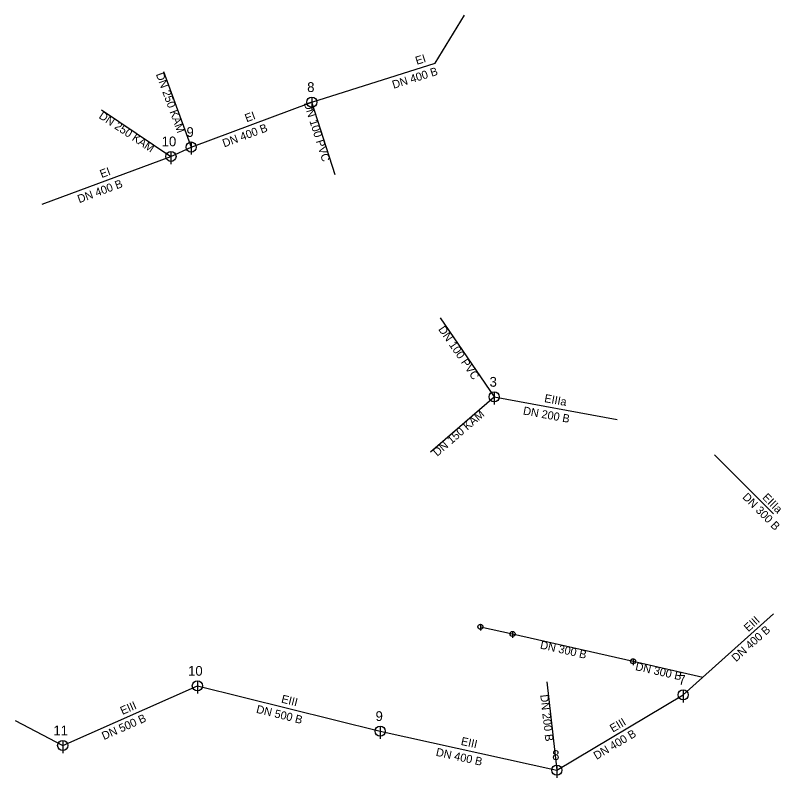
# Model space of a CAD drawing. Extents: x -447725 to -447574, y -1113374 to -1113224.
import ezdxf

# ---------------------------------------------------------------- set-up
doc = ezdxf.new("R2010")
doc.units = 0
for name, color, linetype in [('_pripojka_kanal_jednotna_prevzato_z_dokumentace_', 7, 'Continuous'), ('_pripojka_kanal_jednotna_priblizne_', 7, 'Continuous'), ('_stoka_jednotna_smvak_prevzato_z_dokumentace_', 7, 'Continuous'), ('Default', 7, 'Continuous'), ('MoLevel 119', 7, 'Continuous'), ('MoLevel 120', 7, 'Continuous'), ('MoLevel 124', 7, 'Continuous'), ('MoLevel 126', 7, 'Continuous'), ('MoLevel 57', 7, 'Continuous'), ('MoLevel 68', 7, 'Continuous'), ('MoLevel 69', 7, 'Continuous')]:
    doc.layers.add(name, color=color, linetype=linetype)

# ---------------------------------------------------------------- blocks, each defined once
blk = doc.blocks.new('_sachta_kanal_prip_')
at = {"layer": 'Default'}
blk.add_line((0, 0.00005), (0, -0.000075), dxfattribs=at)
blk.add_circle((0, 0), 0.00005, dxfattribs=at)
blk = doc.blocks.new('_sachta_kanal_prevzato_z_dokumentace_')
at = {"layer": 'Default'}
blk.add_line((0, 0.00005), (0, -0.000075), dxfattribs=at)
blk.add_circle((0, 0), 0.00005, dxfattribs=at)

msp = doc.modelspace()

# ---------------------------------------------------------------- linework, layer by layer
at = {"layer": '_pripojka_kanal_jednotna_prevzato_z_dokumentace_'}
msp.add_line((-447626.69, -1113346.07), (-447602.89, -1113351.46), dxfattribs=at)
at = {"layer": '_pripojka_kanal_jednotna_priblizne_'}
for p, q in [((-447695.62, -1113234.93), (-447690.13, -1113249.88)), ((-447661.72, -1113255.38), (-447666.3, -1113241)), ((-447707.86, -1113242.56), (-447694.11, -1113251.73)), ((-447640.99, -1113283.65), (-447630.29, -1113299.23)), ((-447642.87, -1113310.1), (-447630.29, -1113299.23)), ((-447633.03, -1113344.66), (-447626.69, -1113346.07)), ((-447602.89, -1113351.46), (-447589.09, -1113354.59)), ((-447619.88, -1113355.52), (-447617.93, -1113372.96))]:
    msp.add_line(p, q, dxfattribs=at)
at = {"layer": '_stoka_jednotna_smvak_prevzato_z_dokumentace_'}
for p, q in [((-447690.13, -1113249.88), (-447666.3, -1113241)), ((-447694.11, -1113251.73), (-447690.13, -1113249.88)), ((-447719.55, -1113261.19), (-447694.11, -1113251.73)), ((-447630.29, -1113299.23), (-447606.03, -1113303.7)), ((-447586.79, -1113310.65), (-447575.16, -1113322.36)), ((-447593, -1113358.1), (-447575.16, -1113342.08)), ((-447715.49, -1113368.09), (-447688.9, -1113356.32)), ((-447688.9, -1113356.32), (-447652.8, -1113365.26)), ((-447617.93, -1113372.96), (-447593, -1113358.1)), ((-447724.85, -1113363.18), (-447715.49, -1113368.09)), ((-447652.8, -1113365.26), (-447617.93, -1113372.96))]:
    msp.add_line(p, q, dxfattribs=at)
msp.add_lwpolyline([(-447666.3, -1113241), (-447641.94, -1113233.3), (-447636.17, -1113223.85)], dxfattribs=at)

# ---------------------------------------------------------------- block references
at = {"layer": 'MoLevel 119', "xscale": 20000, "yscale": 20000}
for p in [(-447666.3, -1113241), (-447690.13, -1113249.88), (-447694.11, -1113251.73), (-447630.29, -1113299.23), (-447688.9, -1113356.32), (-447593, -1113358.1), (-447652.8, -1113365.26), (-447715.49, -1113368.09), (-447617.93, -1113372.96)]:
    msp.add_blockref('_sachta_kanal_prevzato_z_dokumentace_', p, dxfattribs=at)
at = {"layer": 'MoLevel 57', "xscale": 10000, "yscale": 10000}
for p in [(-447633.03, -1113344.66), (-447626.69, -1113346.07), (-447602.89, -1113351.46)]:
    msp.add_blockref('_sachta_kanal_prip_', p, dxfattribs=at)

# ---------------------------------------------------------------- texts
at = {"layer": 'MoLevel 120'}
for s, height, p in [('8', 1.93, (-447667.22, -1113239)), ('9', 1.93, (-447691.05, -1113247.88)), ('10', 1.926, (-447695.94, -1113249.73)), ('3', 1.93, (-447631.21, -1113297.23)), ('10', 1.926, (-447690.73, -1113354.32)), ('7', 1.93, (-447593.92, -1113356.1)), ('9', 1.93, (-447653.72, -1113363.26)), ('11', 1.926, (-447717.32, -1113366.09)), ('8', 1.93, (-447618.85, -1113370.96))]:
    msp.add_text(s, height=height, dxfattribs=at).set_placement(p)
at = {"layer": 'MoLevel 124'}
for s, rotation, p in [('DN 250 KAM', 290.1568, (-447697.12, -1113235.5)), ('DN 100 PVC', 287.6787, (-447667.92, -1113241.21)), ('DN 250 KAM', 326.3022, (-447708.49, -1113244.07)), ('DN 100 PVC', 304.4739, (-447641.4, -1113285.89)), ('DN 150 KAM', 40.8151, (-447641.55, -1113311.07)), ('DN 300 B', 347.2402, (-447602.53, -1113353.19)), ('DN 200 B', 276.3853, (-447621.21, -1113358.11))]:
    msp.add_text(s, height=1.605, rotation=rotation, dxfattribs=at).set_placement(p)
at = {"layer": 'MoLevel 126'}
msp.add_text('DN 300 B', height=1.605, rotation=347.2394, dxfattribs=at).set_placement((-447621.33, -1113348.93))
at = {"layer": 'MoLevel 68'}
for s, rotation, p in [('DN 400 B', 17.5372, (-447650.15, -1113238.38)), ('DN 400 B', 20.4374, (-447683.6, -1113249.96)), ('DN 400 B', 20.3979, (-447712.22, -1113260.98)), ('DN 200 B', 349.5601, (-447624.69, -1113302.69)), ('DN 300 B', 314.8182, (-447581.4, -1113319.15)), ('DN 400 B', 41.9198, (-447582.55, -1113351.67)), ('DN 500 B', 346.0908, (-447677.39, -1113361.62)), ('DN 500 B', 23.8765, (-447707.35, -1113367.04)), ('DN 400 B', 30.7979, (-447610.09, -1113370.96)), ('DN 400 B', 347.5478, (-447641.91, -1113370.11))]:
    msp.add_text(s, height=1.605, rotation=rotation, dxfattribs=at).set_placement(p)
at = {"layer": 'MoLevel 69'}
for s, rotation, p in [('EI', 17.5372, (-447645.57, -1113233.65)), ('EI', 20.4374, (-447679.18, -1113245)), ('EI', 20.3979, (-447707.8, -1113256.02)), ('EIIIa', 349.5601, (-447620.49, -1113300.24)), ('EIIIa', 314.8182, (-447577.46, -1113319.23)), ('EIII', 41.9198, (-447580.12, -1113345.74)), ('EIII', 346.0908, (-447672.44, -1113359.6)), ('EIII', 23.8765, (-447703.7, -1113362.07)), ('EIII', 30.7979, (-447606.88, -1113365.57)), ('EIII', 347.5478, (-447636.97, -1113367.96))]:
    msp.add_text(s, height=1.605, rotation=rotation, dxfattribs=at).set_placement(p)

doc.saveas('drawing.dxf')
